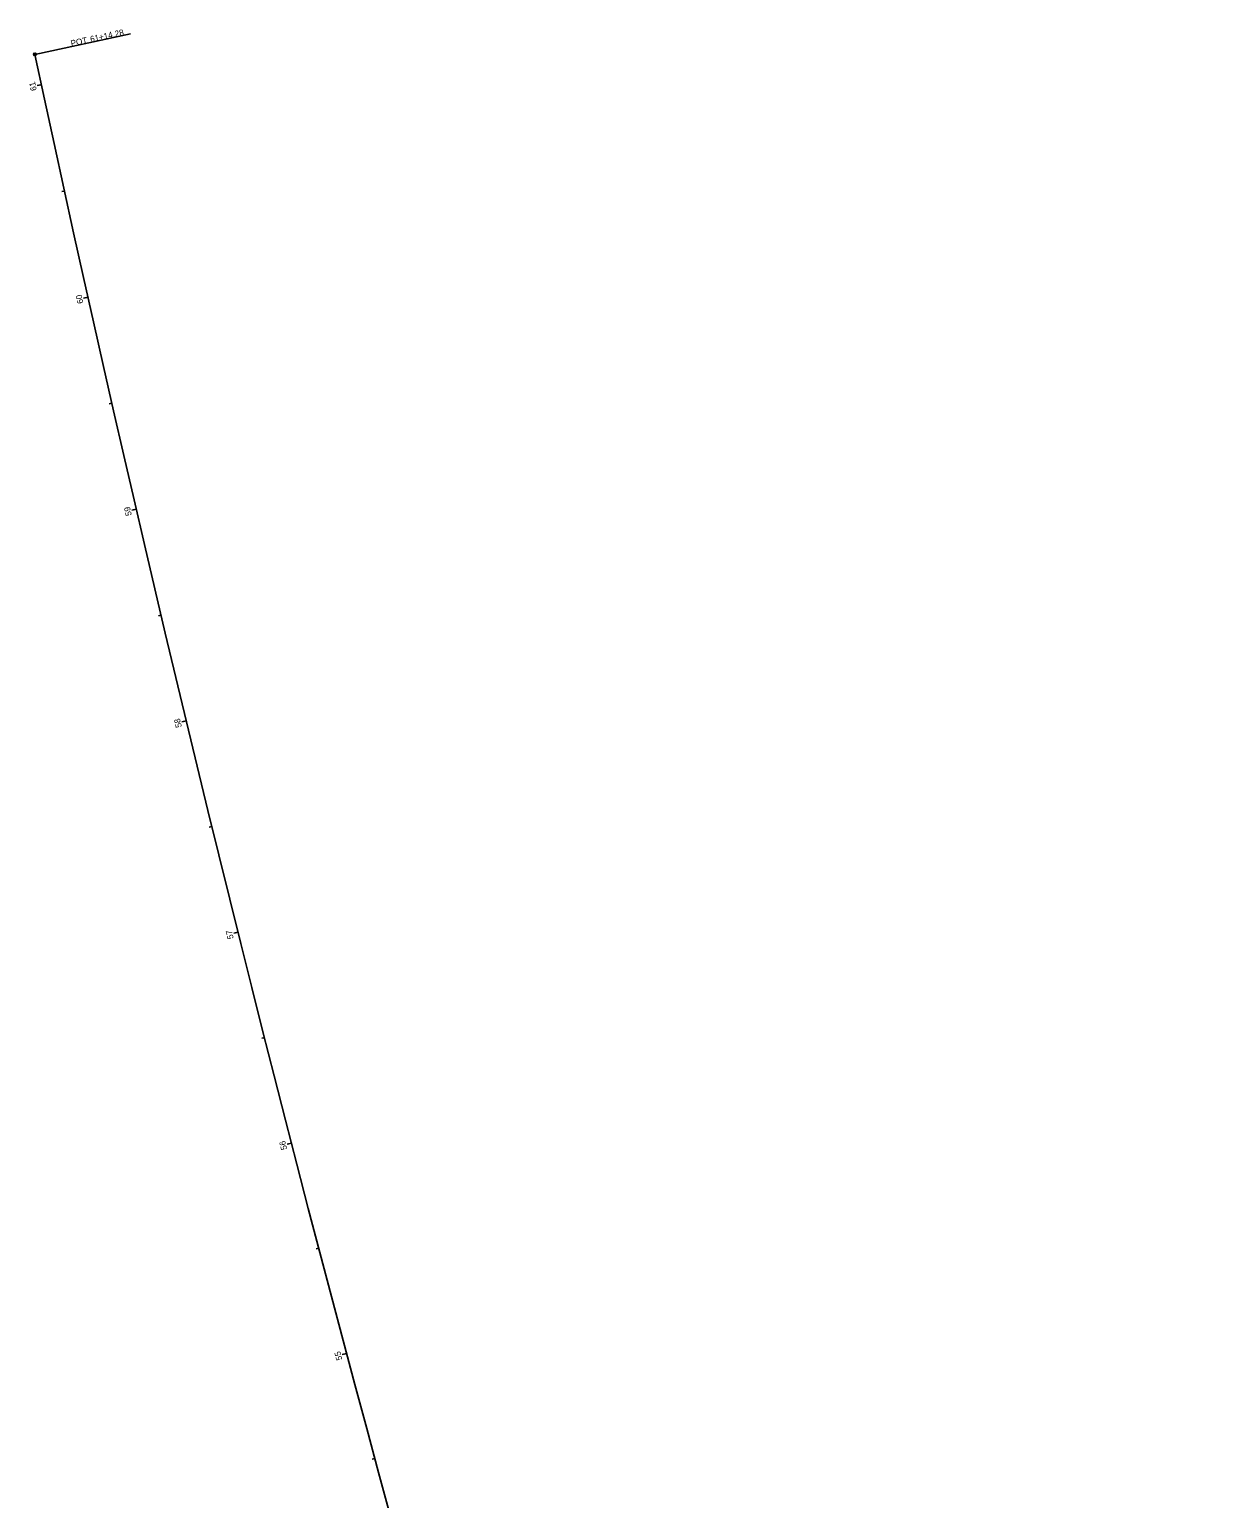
# Model space of a CAD drawing. Extents: x 1362949 to 1365618, y 484963 to 490440.
# Drawn here: x 1362949 to 1363502, y 489764 to 490440 of the extents above; entities that cross this region are included whole.
import ezdxf

# ---------------------------------------------------------------- set-up
doc = ezdxf.new("R2010")
doc.units = 0
for name, color, linetype in [('BR_X_SV_Bottom_of_Beam_Text', 7, 'Continuous'), ('BR_X_SV_Shot_Marker', 7, 'Continuous'), ('Default', 7, 'Continuous'), ('PV_X_Curb', 7, 'Continuous'), ('RD_X_GR_Rt', 7, 'Continuous'), ('SG_X_PullBox', 7, 'Continuous'), ('SV_X_Break_Lines', 7, 'Continuous'), ('SV_X_Text_Name', 7, 'Continuous'), ('UT_X_Unknown_Cells', 7, 'Continuous')]:
    doc.layers.add(name, color=color, linetype=linetype)

msp = doc.modelspace()

# ---------------------------------------------------------------- linework, layer by layer
at = {"layer": 'BR_X_SV_Bottom_of_Beam_Text'}
for p, q in [((1362954.82, 490414.27), (1362952.86, 490413.85)), ((1362965.42, 490365.41), (1362964.25, 490365.15)), ((1362976.23, 490316.59), (1362974.28, 490316.16)), ((1362987.23, 490267.82), (1362986.06, 490267.55)), ((1362998.44, 490219.09), (1362996.49, 490218.64)), ((1363009.84, 490170.41), (1363008.67, 490170.13)), ((1363021.44, 490121.77), (1363019.49, 490121.3)), ((1363033.24, 490073.18), (1363032.07, 490072.9)), ((1363045.23, 490024.64), (1363043.29, 490024.16)), ((1363057.42, 489976.15), (1363056.26, 489975.86)), ((1363069.81, 489927.71), (1363067.88, 489927.21)), ((1363082.4, 489879.32), (1363081.24, 489879.02)), ((1363095.19, 489830.99), (1363093.25, 489830.47)), ((1363108.17, 489782.7), (1363107.01, 489782.39))]:
    msp.add_line(p, q, dxfattribs=at)
at = {"layer": 'BR_X_SV_Shot_Marker'}
msp.add_line((1362951.82, 490428.24), (1362995.83, 490437.64), dxfattribs=at)
msp.add_circle((1362951.82, 490428.24), 0.6, dxfattribs=at)
at = {"layer": 'Default'}
for p, q in [((1362951.16, 490427.58), (1362952.49, 490428.91)), ((1362951.16, 490428.91), (1362952.49, 490427.58))]:
    msp.add_line(p, q, dxfattribs=at)
at = {"layer": 'PV_X_Curb'}
for p, q in [((1362954.82, 490414.27), (1362953.64, 490414.02)), ((1362976.23, 490316.59), (1362974.28, 490316.16)), ((1362976.23, 490316.59), (1362975.06, 490316.33)), ((1362998.44, 490219.09), (1362997.27, 490218.82)), ((1363021.44, 490121.77), (1363020.27, 490121.49)), ((1363045.23, 490024.64), (1363044.07, 490024.35)), ((1363069.81, 489927.71), (1363068.65, 489927.41)), ((1363095.19, 489830.99), (1363093.25, 489830.47)), ((1363095.19, 489830.99), (1363094.03, 489830.68))]:
    msp.add_line(p, q, dxfattribs=at)
at = {"layer": 'RD_X_GR_Rt'}
msp.add_line((1362951.82, 490428.24), (1362995.83, 490437.64), dxfattribs=at)
msp.add_circle((1362951.82, 490428.24), 0.6, dxfattribs=at)
at = {"layer": 'SG_X_PullBox'}
msp.add_line((1362951.82, 490428.24), (1362995.83, 490437.64), dxfattribs=at)
msp.add_circle((1362951.82, 490428.24), 0.6, dxfattribs=at)
at = {"layer": 'SV_X_Break_Lines'}
for p, q in [((1362976.23, 490316.59), (1362974.28, 490316.16)), ((1362976.23, 490316.59), (1362975.06, 490316.33)), ((1363095.19, 489830.99), (1363094.03, 489830.68))]:
    msp.add_line(p, q, dxfattribs=at)
at = {"layer": 'SV_X_Text_Name'}
msp.add_arc((1374958.32, 492994.42), 12277.67, 192.064501, 217.049501, dxfattribs=at)
at = {"layer": 'UT_X_Unknown_Cells'}
msp.add_arc((1374958.32, 492994.42), 12277.67, 192.064501, 217.049501, dxfattribs=at)

# ---------------------------------------------------------------- texts
at = {"layer": 'BR_X_SV_Bottom_of_Beam_Text'}
for s, rotation, p in [('61', 102.13114, (1362952.75, 490411.76)), ('60', 102.59781, (1362974.22, 490313.9)), ('59', 103.06447, (1362996.45, 490216.41)), ('58', 103.53114, (1363019.47, 490119.05)), ('57', 103.99781, (1363043.3, 490021.84)), ('56', 104.46447, (1363067.9, 489924.95)), ('55', 104.93114, (1363093.29, 489828.2))]:
    msp.add_text(s, height=2.8, rotation=rotation, dxfattribs=at).set_placement(p)
at = {"layer": 'BR_X_SV_Shot_Marker'}
for s, p in [('POT', (1362968.64, 490431.88)), ('61+14.28', (1362977.57, 490433.79))]:
    msp.add_text(s, height=2.8, rotation=12.0645, dxfattribs=at).set_placement(p)
at = {"layer": 'PV_X_Curb'}
for s, rotation, p in [('60', 102.59781, (1362974.22, 490313.9)), ('55', 104.93114, (1363093.29, 489828.2))]:
    msp.add_text(s, height=2.8, rotation=rotation, dxfattribs=at).set_placement(p)
at = {"layer": 'RD_X_GR_Rt'}
for s, p in [('POT', (1362968.64, 490431.88)), ('61+14.28', (1362977.57, 490433.79))]:
    msp.add_text(s, height=2.8, rotation=12.0645, dxfattribs=at).set_placement(p)
at = {"layer": 'SG_X_PullBox'}
for s, p in [('POT', (1362968.64, 490431.88)), ('61+14.28', (1362977.57, 490433.79))]:
    msp.add_text(s, height=2.8, rotation=12.0645, dxfattribs=at).set_placement(p)
at = {"layer": 'SV_X_Break_Lines'}
msp.add_text('60', height=2.8, rotation=102.59781, dxfattribs=at).set_placement((1362974.22, 490313.9))

doc.saveas('drawing.dxf')
